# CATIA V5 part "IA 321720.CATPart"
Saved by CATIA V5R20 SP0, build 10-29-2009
Part number: IA 321720
Revision: ANY
Definition: UNKNOWN
Nomenclature: IA 321720
Source: Unknown
Bounding box of the stored display mesh (mm): x -1.6 to 1.6, y -8.75 to 8.2, z -1.6 to 1.6
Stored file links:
  C:\Users\Utente\Desktop\IO LAVORO\3D X SITO CF\CUMSA\3D files IA\IA 321720\IA 321720.CATPart
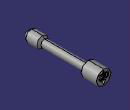
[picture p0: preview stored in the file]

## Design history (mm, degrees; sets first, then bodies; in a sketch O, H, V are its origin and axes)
Body1 "Cortar-Extruir4" (main body)
  Solid1: solid without history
